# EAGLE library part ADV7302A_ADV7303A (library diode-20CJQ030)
Analog Device ADV7302A/ADV7303A Multiformat SD, Progressive Scan/HDTV Video Encoder with Six 11-Bit DACs DESCRIPTION: The ADV7302A/ADV7303A is a high speed, digital-to-analog encoder on a single monolithic chip. It includes six high speed video D/A converters with TTL compatible inputs. The ADV7302A/ADV7303A has three separate 8-bit wide input ports that accept data in high definition and/or standard definition video format. For all standards, external horizontal, vertical, and blanking signals, or EAV/SAV timing codes, control the insertion of appropriate synchronization signals into the digital data stream and therefore the output signals. FEATURES: High Definition Input Formats: - YCrCb Compliant to SMPTE293M (525 p), ITU-R.BT1358 (625 p), SMPTE274M (1080 i), SMPTE296M (720 p), and Any Other High Definition Standard Using Async Timing Mode - RGB in 3 8-Bit 4:4:4 Format - BTA T-1004 EDTV2 525 p Parallel High Definition Output Formats (525 p/625 p/720 p/1080 i) - YPrPb Progressive Scan (EIA-770.1, EIA-770.2) - YPrPb HDTV (EIA 770.3) - RGB + H/V (HDTV 5-Wire Format) - CGMS-A (720 p/1080 i) - Macrovision Rev 1.0 (525 p/625 p)* CGMS-A (525 p) Standard Definition Input Formats: - CCIR-656 4:2:2 8-Bit Parallel Input - CCIR-601 4:2:2 16-Bit Parallel Input Standard Definition Output Formats: - Composite NTSC M, N; - PAL M, N, B, D, G, H, I, PAL-60 - SMPTE170M NTSC Compatible Composite Video - ITU-R.BT470 PAL Compatible Composite Video - S-Video (Y/C) - EuroScart RGB - Component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
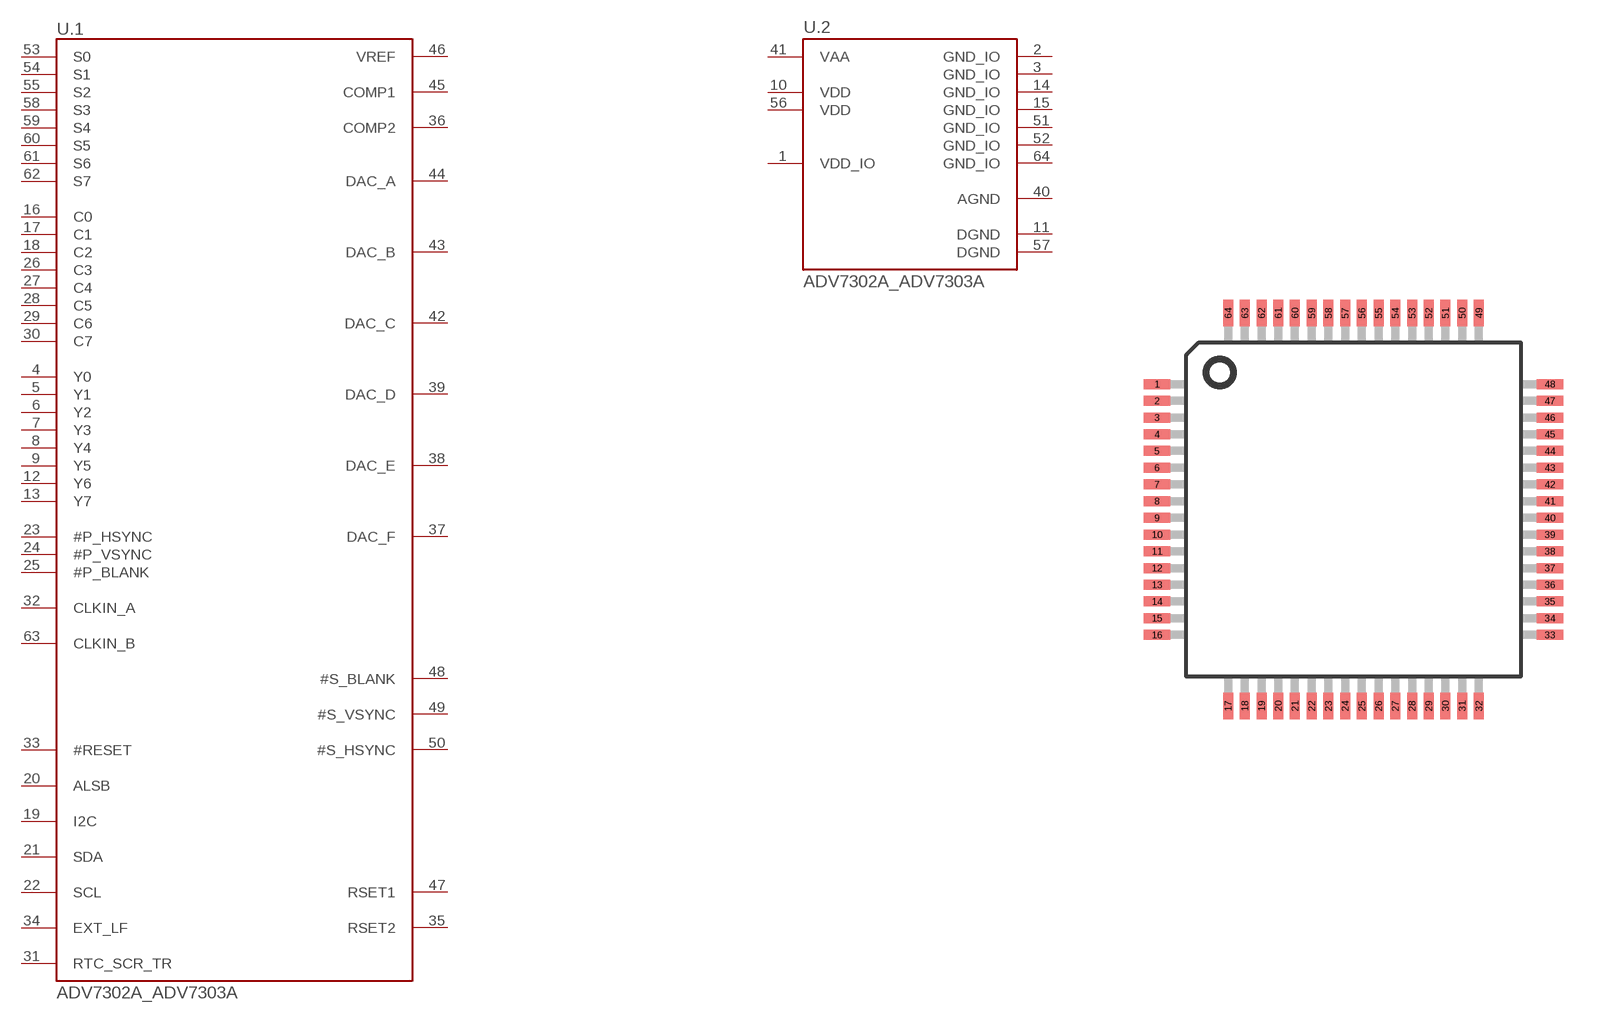
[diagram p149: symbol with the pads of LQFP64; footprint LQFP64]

Designator prefix U; gates .1=ADV7302A_ADV7303A .2=ADV7302A_ADV7303A_PWR

## ADV7302A_ADV7303A  [LQFP64]
1  .2:VDD_IO  pwr
2  .2:GND_IO  pwr
3  .2:GND_IO  pwr
4  .1:Y0  in
5  .1:Y1  in
6  .1:Y2  in
7  .1:Y3  in
8  .1:Y4  in
9  .1:Y5  in
10  .2:VDD  pwr
11  .2:DGND  pwr
12  .1:Y6  in
13  .1:Y7  in
14  .2:GND_IO  pwr
15  .2:GND_IO  pwr
16  .1:C0  in
17  .1:C1  in
18  .1:C2  in
19  .1:I2C  in
20  .1:ALSB
21  .1:SDA
22  .1:SCL  in
23  .1:#P_HSYNC
24  .1:#P_VSYNC
25  .1:#P_BLANK
26  .1:C3  in
27  .1:C4  in
28  .1:C5  in
29  .1:C6  in
30  .1:C7  in
31  .1:RTC_SCR_TR  in
32  .1:CLKIN_A  in
33  .1:#RESET  in
34  .1:EXT_LF  in
35  .1:RSET2  in
36  .1:COMP2  out
37  .1:DAC_F  out
38  .1:DAC_E  out
39  .1:DAC_D  out
40  .2:AGND  pwr
41  .2:VAA  pwr
42  .1:DAC_C  out
43  .1:DAC_B  out
44  .1:DAC_A  out
45  .1:COMP1  out
46  .1:VREF
47  .1:RSET1  in
48  .1:#S_BLANK
49  .1:#S_VSYNC
50  .1:#S_HSYNC
51  .2:GND_IO  pwr
52  .2:GND_IO  pwr
53  .1:S0  in
54  .1:S1  in
55  .1:S2  in
56  .2:VDD  pwr
57  .2:DGND  pwr
58  .1:S3  in
59  .1:S4  in
60  .1:S5  in
61  .1:S6  in
62  .1:S7  in
63  .1:CLKIN_B  in
64  .2:GND_IO  pwr

## Footprint LQFP64 (pad centres in mm)
Analog's 64-Lead Thin Plastic Quad Flatpack [LQFP] (ST-64B)
smd 0.8 x 0.3: 1 -5.875,3.75; 2 -5.875,3.25; 3 -5.875,2.75; 4 -5.875,2.25; 5 -5.875,1.75; 6 -5.875,1.25; 7 -5.875,0.75; 8 -5.875,0.25; 9 -5.875,-0.25; 10 -5.875,-0.75; 11 -5.875,-1.25; 12 -5.875,-1.75; 13 -5.875,-2.25; 14 -5.875,-2.75; 15 -5.875,-3.25; 16 -5.875,-3.75; 33 5.875,-3.75; 34 5.875,-3.25; 35 5.875,-2.75; 36 5.875,-2.25; 37 5.875,-1.75; 38 5.875,-1.25; 39 5.875,-0.75; 40 5.875,-0.25; 41 5.875,0.25; 42 5.875,0.75; 43 5.875,1.25; 44 5.875,1.75; 45 5.875,2.25; 46 5.875,2.75; 47 5.875,3.25; 48 5.875,3.75
smd 0.3 x 0.8: 17 -3.75,-5.875; 18 -3.25,-5.875; 19 -2.75,-5.875; 20 -2.25,-5.875; 21 -1.75,-5.875; 22 -1.25,-5.875; 23 -0.75,-5.875; 24 -0.25,-5.875; 25 0.25,-5.875; 26 0.75,-5.875; 27 1.25,-5.875; 28 1.75,-5.875; 29 2.25,-5.875; 30 2.75,-5.875; 31 3.25,-5.875; 32 3.75,-5.875; 49 3.75,5.875; 50 3.25,5.875; 51 2.75,5.875; 52 2.25,5.875; 53 1.75,5.875; 54 1.25,5.875; 55 0.75,5.875; 56 0.25,5.875; 57 -0.25,5.875; 58 -0.75,5.875; 59 -1.25,5.875; 60 -1.75,5.875; 61 -2.25,5.875; 62 -2.75,5.875; 63 -3.25,5.875; 64 -3.75,5.875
